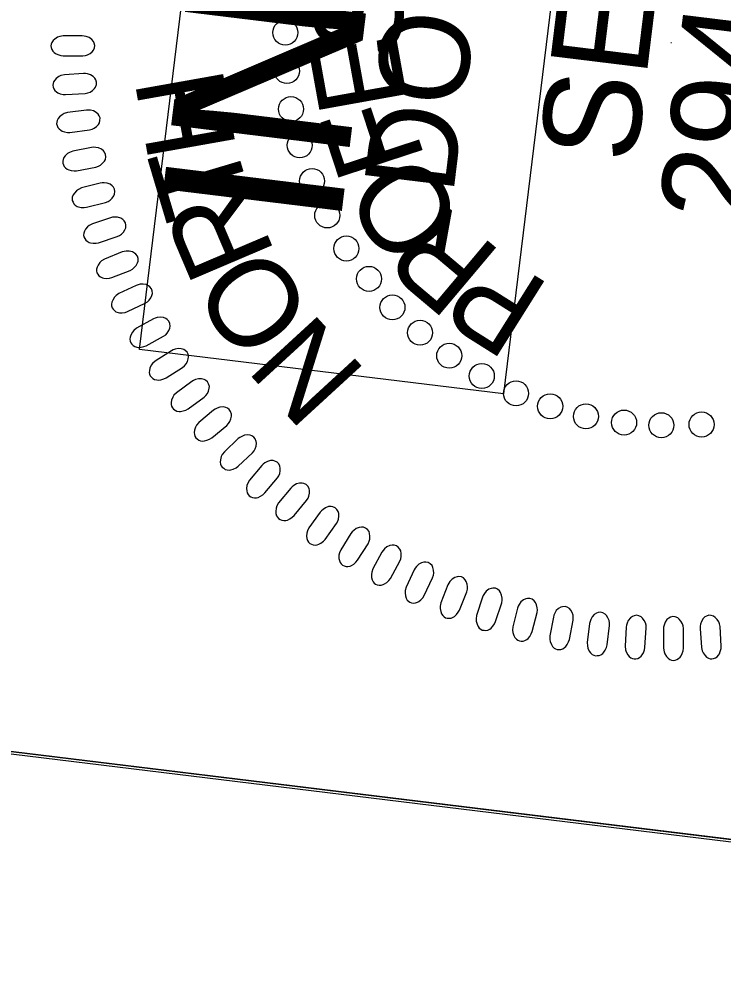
# Model space of a CAD drawing. Extents: x 480570 to 481861, y 488765 to 490569.
# Drawn here: x 480835.4 to 480880.5, y 490328.8 to 490389.3 of the extents above; entities that cross this region are included whole.
import ezdxf

# ---------------------------------------------------------------- set-up
doc = ezdxf.new("R2010")
doc.units = 0
for name, color, linetype in [('Sheet Clip Boundary CELL', 7, 'Continuous'), ('Sheet PE Seal Cell', 7, 'Continuous'), ('Sheet Plan CELL', 7, 'Continuous'), ('Sheet Sticker Incomplete CELL', 7, 'Continuous')]:
    doc.layers.add(name, color=color, linetype=linetype)

msp = doc.modelspace()

# ---------------------------------------------------------------- linework, layer by layer
at = {"layer": 'Sheet Clip Boundary CELL'}
msp.add_lwpolyline([(481654.789, 488932.477), (481815.956, 490252.137), (481655.102, 490245.276), (481542.679, 490356.599), (481123.704, 490407.772), (480954.544, 490428.587), (480942.398, 490329.137), (480942.398, 490329.137), (480770.14, 490350.174), (480612.545, 489059.764)], close=True, dxfattribs=at)
at = {"layer": 'Sheet PE Seal Cell'}
msp.add_line((480877.203, 490387.81), (480877.249, 490387.805), dxfattribs=at)
for points in [[(480839.503, 490388.241), (480838.276, 490388.237), (480838.057, 490388.199), (480837.918, 490388.146), (480837.748, 490388.033), (480837.639, 490387.935), (480837.56, 490387.823), (480837.52, 490387.718), (480837.5, 490387.606), (480837.521, 490387.494), (480837.551, 490387.374), (480837.611, 490387.27), (480837.712, 490387.165), (480837.792, 490387.106), (480837.941, 490387.039), (480838.121, 490386.98), (480838.281, 490386.958), (480839.537, 490386.956), (480839.707, 490386.979), (480839.847, 490387.024), (480840.006, 490387.114), (480840.145, 490387.227), (480840.224, 490387.325), (480840.284, 490387.482), (480840.303, 490387.631), (480840.263, 490387.78), (480840.212, 490387.885), (480840.112, 490388.012), (480839.942, 490388.131), (480839.762, 490388.197), (480839.633, 490388.226)], [(480839.579, 490385.833), (480838.356, 490385.752), (480838.139, 490385.7), (480838.003, 490385.638), (480837.841, 490385.515), (480837.739, 490385.411), (480837.666, 490385.294), (480837.634, 490385.187), (480837.621, 490385.073), (480837.648, 490384.963), (480837.686, 490384.846), (480837.753, 490384.745), (480837.86, 490384.647), (480837.943, 490384.593), (480838.097, 490384.536), (480838.28, 490384.488), (480838.44, 490384.476), (480839.695, 490384.552), (480839.863, 490384.586), (480839.999, 490384.64), (480840.152, 490384.74), (480840.284, 490384.861), (480840.357, 490384.964), (480840.406, 490385.124), (480840.416, 490385.274), (480840.366, 490385.421), (480840.31, 490385.522), (480840.202, 490385.642), (480840.025, 490385.751), (480839.841, 490385.806), (480839.71, 490385.826)], [(480839.768, 490383.487), (480838.552, 490383.329), (480838.339, 490383.264), (480838.207, 490383.194), (480838.054, 490383.061), (480837.958, 490382.95), (480837.893, 490382.829), (480837.866, 490382.72), (480837.861, 490382.606), (480837.895, 490382.497), (480837.941, 490382.383), (480838.014, 490382.287), (480838.126, 490382.196), (480838.213, 490382.147), (480838.37, 490382.099), (480838.556, 490382.063), (480838.717, 490382.061), (480839.964, 490382.216), (480840.129, 490382.26), (480840.262, 490382.323), (480840.408, 490382.433), (480840.533, 490382.562), (480840.599, 490382.668), (480840.638, 490382.832), (480840.639, 490382.983), (480840.58, 490383.126), (480840.517, 490383.223), (480840.401, 490383.336), (480840.218, 490383.433), (480840.031, 490383.476), (480839.899, 490383.489)], [(480840.101, 490381.096), (480838.897, 490380.861), (480838.689, 490380.783), (480838.562, 490380.705), (480838.417, 490380.563), (480838.328, 490380.446), (480838.271, 490380.321), (480838.252, 490380.21), (480838.254, 490380.097), (480838.294, 490379.99), (480838.347, 490379.879), (480838.425, 490379.788), (480838.543, 490379.704), (480838.633, 490379.66), (480838.793, 490379.623), (480838.98, 490379.598), (480839.142, 490379.607), (480840.376, 490379.839), (480840.538, 490379.894), (480840.667, 490379.965), (480840.806, 490380.083), (480840.922, 490380.22), (480840.982, 490380.33), (480841.01, 490380.496), (480841.001, 490380.647), (480840.934, 490380.786), (480840.865, 490380.879), (480840.743, 490380.985), (480840.553, 490381.07), (480840.364, 490381.101), (480840.231, 490381.106)], [(480840.645, 490378.812), (480839.458, 490378.503), (480839.255, 490378.411), (480839.133, 490378.326), (480838.997, 490378.174), (480838.915, 490378.053), (480838.867, 490377.924), (480838.854, 490377.813), (480838.864, 490377.699), (480838.911, 490377.595), (480838.97, 490377.487), (480839.054, 490377.401), (480839.177, 490377.325), (480839.27, 490377.287), (480839.432, 490377.26), (480839.62, 490377.247), (480839.78, 490377.266), (480840.998, 490377.576), (480841.156, 490377.64), (480841.28, 490377.719), (480841.412, 490377.846), (480841.519, 490377.989), (480841.572, 490378.104), (480841.59, 490378.271), (480841.571, 490378.421), (480841.495, 490378.555), (480841.42, 490378.643), (480841.292, 490378.742), (480841.098, 490378.815), (480840.907, 490378.834), (480840.774, 490378.831)], [(480841.314, 490376.597), (480840.149, 490376.214), (480839.952, 490376.11), (480839.836, 490376.016), (480839.709, 490375.857), (480839.636, 490375.73), (480839.595, 490375.599), (480839.59, 490375.487), (480839.606, 490375.374), (480839.66, 490375.274), (480839.726, 490375.17), (480839.815, 490375.089), (480839.943, 490375.021), (480840.037, 490374.989), (480840.2, 490374.972), (480840.39, 490374.971), (480840.548, 490375), (480841.744, 490375.386), (480841.898, 490375.46), (480842.017, 490375.546), (480842.14, 490375.681), (480842.238, 490375.832), (480842.283, 490375.948), (480842.291, 490376.116), (480842.263, 490376.265), (480842.178, 490376.394), (480842.098, 490376.478), (480841.964, 490376.567), (480841.766, 490376.628), (480841.574, 490376.636), (480841.441, 490376.624)], [(480842.068, 490374.407), (480840.929, 490373.95), (480840.739, 490373.834), (480840.629, 490373.734), (480840.513, 490373.567), (480840.447, 490373.436), (480840.415, 490373.303), (480840.417, 490373.191), (480840.44, 490373.079), (480840.5, 490372.982), (480840.572, 490372.882), (480840.666, 490372.807), (480840.798, 490372.747), (480840.894, 490372.721), (480841.058, 490372.714), (480841.248, 490372.725), (480841.404, 490372.764), (480842.573, 490373.224), (480842.722, 490373.308), (480842.835, 490373.402), (480842.949, 490373.544), (480843.038, 490373.7), (480843.076, 490373.82), (480843.073, 490373.988), (480843.036, 490374.134), (480842.944, 490374.258), (480842.858, 490374.337), (480842.718, 490374.418), (480842.517, 490374.465), (480842.325, 490374.462), (480842.194, 490374.441)], [(480842.957, 490372.266), (480841.849, 490371.739), (480841.666, 490371.611), (480841.563, 490371.504), (480841.457, 490371.33), (480841.4, 490371.195), (480841.376, 490371.06), (480841.385, 490370.948), (480841.415, 490370.838), (480841.481, 490370.745), (480841.56, 490370.651), (480841.658, 490370.582), (480841.793, 490370.53), (480841.891, 490370.51), (480842.056, 490370.513), (480842.243, 490370.537), (480842.397, 490370.584), (480843.535, 490371.117), (480843.679, 490371.21), (480843.786, 490371.311), (480843.891, 490371.46), (480843.969, 490371.621), (480844, 490371.743), (480843.986, 490371.911), (480843.94, 490372.054), (480843.84, 490372.172), (480843.75, 490372.246), (480843.606, 490372.318), (480843.401, 490372.353), (480843.21, 490372.336), (480843.08, 490372.308)], [(480844.059, 490370.116), (480842.986, 490369.52), (480842.812, 490369.381), (480842.715, 490369.268), (480842.621, 490369.087), (480842.573, 490368.949), (480842.557, 490368.813), (480842.573, 490368.701), (480842.61, 490368.594), (480842.682, 490368.506), (480842.766, 490368.416), (480842.869, 490368.353), (480843.007, 490368.31), (480843.106, 490368.296), (480843.27, 490368.31), (480843.455, 490368.345), (480843.606, 490368.403), (480844.708, 490369.005), (480844.846, 490369.108), (480844.946, 490369.214), (480845.042, 490369.37), (480845.11, 490369.536), (480845.133, 490369.66), (480845.108, 490369.826), (480845.053, 490369.966), (480844.946, 490370.078), (480844.852, 490370.145), (480844.703, 490370.208), (480844.496, 490370.23), (480844.307, 490370.202), (480844.179, 490370.165)], [(480845.209, 490368.08), (480844.176, 490367.419), (480844.011, 490367.269), (480843.922, 490367.15), (480843.84, 490366.964), (480843.799, 490366.824), (480843.792, 490366.686), (480843.816, 490366.576), (480843.859, 490366.471), (480843.937, 490366.387), (480844.026, 490366.303), (480844.133, 490366.246), (480844.274, 490366.212), (480844.373, 490366.205), (480844.535, 490366.229), (480844.718, 490366.275), (480844.866, 490366.343), (480845.928, 490367.013), (480846.058, 490367.124), (480846.152, 490367.237), (480846.238, 490367.398), (480846.295, 490367.568), (480846.31, 490367.693), (480846.275, 490367.857), (480846.211, 490367.994), (480846.097, 490368.098), (480845.999, 490368.16), (480845.847, 490368.213), (480845.639, 490368.222), (480845.452, 490368.182), (480845.326, 490368.137)], [(480846.52, 490366.119), (480845.53, 490365.394), (480845.375, 490365.235), (480845.293, 490365.11), (480845.223, 490364.919), (480845.192, 490364.776), (480845.193, 490364.639), (480845.223, 490364.53), (480845.273, 490364.428), (480845.356, 490364.35), (480845.451, 490364.271), (480845.561, 490364.221), (480845.703, 490364.196), (480845.803, 490364.195), (480845.963, 490364.229), (480846.143, 490364.287), (480846.285, 490364.363), (480847.304, 490365.1), (480847.427, 490365.217), (480847.513, 490365.336), (480847.589, 490365.503), (480847.636, 490365.677), (480847.643, 490365.802), (480847.598, 490365.964), (480847.525, 490366.096), (480847.405, 490366.193), (480847.303, 490366.248), (480847.148, 490366.292), (480846.94, 490366.288), (480846.755, 490366.236), (480846.633, 490366.184)], [(480847.916, 490364.274), (480846.974, 490363.489), (480846.829, 490363.319), (480846.755, 490363.19), (480846.696, 490362.995), (480846.674, 490362.85), (480846.685, 490362.713), (480846.722, 490362.607), (480846.778, 490362.508), (480846.865, 490362.435), (480846.965, 490362.362), (480847.077, 490362.32), (480847.221, 490362.303), (480847.321, 490362.309), (480847.479, 490362.352), (480847.655, 490362.422), (480847.792, 490362.506), (480848.762, 490363.305), (480848.878, 490363.431), (480848.956, 490363.555), (480849.021, 490363.726), (480849.057, 490363.901), (480849.056, 490364.027), (480849.002, 490364.186), (480848.921, 490364.314), (480848.794, 490364.403), (480848.69, 490364.451), (480848.531, 490364.485), (480848.324, 490364.469), (480848.143, 490364.405), (480848.025, 490364.345)], [(480849.494, 490362.456), (480848.603, 490361.613), (480848.469, 490361.435), (480848.403, 490361.301), (480848.357, 490361.103), (480848.344, 490360.957), (480848.364, 490360.821), (480848.406, 490360.718), (480848.469, 490360.622), (480848.561, 490360.554), (480848.665, 490360.488), (480848.78, 490360.453), (480848.924, 490360.446), (480849.023, 490360.457), (480849.178, 490360.511), (480849.35, 490360.591), (480849.481, 490360.684), (480850.399, 490361.542), (480850.507, 490361.675), (480850.577, 490361.804), (480850.632, 490361.979), (480850.656, 490362.156), (480850.647, 490362.282), (480850.582, 490362.437), (480850.495, 490362.558), (480850.363, 490362.64), (480850.255, 490362.682), (480850.095, 490362.706), (480849.89, 490362.676), (480849.713, 490362.602), (480849.598, 490362.534)], [(480850.998, 490360.736), (480850.213, 490359.794), (480850.101, 490359.601), (480850.051, 490359.461), (480850.029, 490359.259), (480850.033, 490359.112), (480850.068, 490358.98), (480850.123, 490358.882), (480850.197, 490358.795), (480850.295, 490358.738), (480850.407, 490358.685), (480850.525, 490358.663), (480850.669, 490358.673), (480850.766, 490358.696), (480850.914, 490358.768), (480851.075, 490358.867), (480851.194, 490358.975), (480852.005, 490359.935), (480852.096, 490360.08), (480852.151, 490360.216), (480852.185, 490360.396), (480852.188, 490360.575), (480852.164, 490360.698), (480852.082, 490360.845), (480851.98, 490360.956), (480851.84, 490361.021), (480851.728, 490361.05), (480851.566, 490361.055), (480851.366, 490361.001), (480851.199, 490360.907), (480851.093, 490360.826)], [(480852.859, 490359.285), (480852.081, 490358.337), (480851.97, 490358.144), (480851.922, 490358.003), (480851.901, 490357.8), (480851.907, 490357.654), (480851.942, 490357.521), (480851.998, 490357.424), (480852.072, 490357.337), (480852.172, 490357.282), (480852.283, 490357.229), (480852.402, 490357.209), (480852.546, 490357.22), (480852.643, 490357.243), (480852.79, 490357.316), (480852.95, 490357.417), (480853.068, 490357.526), (480853.872, 490358.493), (480853.962, 490358.638), (480854.016, 490358.774), (480854.048, 490358.954), (480854.05, 490359.133), (480854.025, 490359.257), (480853.942, 490359.403), (480853.839, 490359.513), (480853.698, 490359.577), (480853.586, 490359.605), (480853.424, 490359.609), (480853.224, 490359.553), (480853.058, 490359.457), (480852.952, 490359.376)], [(480854.735, 490357.743), (480854.017, 490356.747), (480853.92, 490356.548), (480853.88, 490356.404), (480853.872, 490356.201), (480853.887, 490356.055), (480853.931, 490355.925), (480853.993, 490355.831), (480854.072, 490355.749), (480854.175, 490355.7), (480854.289, 490355.654), (480854.409, 490355.642), (480854.552, 490355.662), (480854.647, 490355.691), (480854.789, 490355.773), (480854.943, 490355.884), (480855.055, 490356), (480855.795, 490357.015), (480855.876, 490357.165), (480855.921, 490357.305), (480855.942, 490357.487), (480855.933, 490357.666), (480855.9, 490357.788), (480855.808, 490357.928), (480855.698, 490358.031), (480855.554, 490358.086), (480855.44, 490358.107), (480855.278, 490358.101), (480855.083, 490358.033), (480854.923, 490357.927), (480854.823, 490357.839)], [(480856.709, 490356.385), (480856.055, 490355.346), (480855.97, 490355.141), (480855.939, 490354.995), (480855.944, 490354.791), (480855.968, 490354.647), (480856.02, 490354.52), (480856.088, 490354.43), (480856.172, 490354.353), (480856.278, 490354.311), (480856.395, 490354.272), (480856.515, 490354.267), (480856.657, 490354.296), (480856.75, 490354.332), (480856.887, 490354.422), (480857.033, 490354.543), (480857.137, 490354.665), (480857.813, 490355.726), (480857.884, 490355.881), (480857.92, 490356.023), (480857.929, 490356.205), (480857.908, 490356.383), (480857.869, 490356.502), (480857.768, 490356.637), (480857.652, 490356.733), (480857.504, 490356.779), (480857.389, 490356.793), (480857.229, 490356.776), (480857.037, 490356.696), (480856.885, 490356.58), (480856.79, 490356.486)], [(480858.698, 490355.195), (480858.111, 490354.118), (480858.039, 490353.907), (480858.017, 490353.76), (480858.035, 490353.557), (480858.068, 490353.414), (480858.128, 490353.291), (480858.202, 490353.206), (480858.29, 490353.134), (480858.398, 490353.099), (480858.518, 490353.068), (480858.638, 490353.07), (480858.777, 490353.107), (480858.868, 490353.149), (480858.999, 490353.248), (480859.137, 490353.377), (480859.233, 490353.506), (480859.841, 490354.606), (480859.902, 490354.766), (480859.93, 490354.91), (480859.928, 490355.093), (480859.896, 490355.269), (480859.849, 490355.386), (480859.74, 490355.514), (480859.618, 490355.602), (480859.468, 490355.639), (480859.351, 490355.645), (480859.192, 490355.619), (480859.007, 490355.527), (480858.861, 490355.401), (480858.773, 490355.301)], [(480860.765, 490354.06), (480860.247, 490352.948), (480860.188, 490352.734), (480860.176, 490352.585), (480860.206, 490352.384), (480860.248, 490352.243), (480860.316, 490352.124), (480860.393, 490352.044), (480860.487, 490351.978), (480860.597, 490351.949), (480860.718, 490351.925), (480860.838, 490351.935), (480860.975, 490351.981), (480861.063, 490352.029), (480861.188, 490352.136), (480861.317, 490352.273), (480861.405, 490352.408), (480861.943, 490353.544), (480861.994, 490353.707), (480862.012, 490353.853), (480861.998, 490354.035), (480861.955, 490354.209), (480861.902, 490354.323), (480861.785, 490354.443), (480861.657, 490354.525), (480861.505, 490354.551), (480861.389, 490354.55), (480861.231, 490354.514), (480861.052, 490354.411), (480860.915, 490354.276), (480860.833, 490354.171)], [(480862.918, 490353.088), (480862.471, 490351.945), (480862.426, 490351.727), (480862.423, 490351.578), (480862.466, 490351.379), (480862.516, 490351.242), (480862.591, 490351.126), (480862.675, 490351.051), (480862.772, 490350.991), (480862.883, 490350.969), (480863.006, 490350.953), (480863.125, 490350.971), (480863.258, 490351.026), (480863.344, 490351.078), (480863.461, 490351.193), (480863.582, 490351.339), (480863.661, 490351.479), (480864.126, 490352.646), (480864.167, 490352.812), (480864.176, 490352.959), (480864.151, 490353.14), (480864.098, 490353.311), (480864.036, 490353.421), (480863.912, 490353.534), (480863.78, 490353.607), (480863.626, 490353.624), (480863.51, 490353.616), (480863.355, 490353.569), (480863.183, 490353.455), (480863.054, 490353.312), (480862.98, 490353.202)], [(480865.135, 490352.302), (480864.76, 490351.134), (480864.729, 490350.913), (480864.735, 490350.764), (480864.791, 490350.568), (480864.849, 490350.434), (480864.932, 490350.324), (480865.019, 490350.254), (480865.12, 490350.201), (480865.233, 490350.186), (480865.356, 490350.178), (480865.474, 490350.202), (480865.604, 490350.266), (480865.685, 490350.323), (480865.796, 490350.445), (480865.907, 490350.598), (480865.977, 490350.743), (480866.369, 490351.938), (480866.398, 490352.106), (480866.398, 490352.252), (480866.362, 490352.431), (480866.298, 490352.599), (480866.229, 490352.704), (480866.098, 490352.809), (480865.962, 490352.874), (480865.807, 490352.882), (480865.692, 490352.866), (480865.541, 490352.81), (480865.375, 490352.685), (480865.256, 490352.535), (480865.188, 490352.42)], [(480867.381, 490351.604), (480867.081, 490350.414), (480867.063, 490350.193), (480867.079, 490350.044), (480867.146, 490349.852), (480867.213, 490349.722), (480867.303, 490349.617), (480867.395, 490349.553), (480867.499, 490349.506), (480867.612, 490349.498), (480867.736, 490349.498), (480867.851, 490349.53), (480867.977, 490349.601), (480868.055, 490349.664), (480868.157, 490349.792), (480868.259, 490349.952), (480868.32, 490350.101), (480868.635, 490351.317), (480868.654, 490351.488), (480868.645, 490351.633), (480868.598, 490351.81), (480868.523, 490351.973), (480868.448, 490352.074), (480868.311, 490352.171), (480868.17, 490352.227), (480868.016, 490352.225), (480867.902, 490352.202), (480867.754, 490352.137), (480867.597, 490352.001), (480867.488, 490351.844), (480867.427, 490351.725)], [(480869.673, 490351.035), (480869.448, 490349.829), (480869.444, 490349.606), (480869.47, 490349.459), (480869.548, 490349.272), (480869.624, 490349.146), (480869.72, 490349.048), (480869.815, 490348.989), (480869.922, 490348.949), (480870.035, 490348.948), (480870.159, 490348.956), (480870.272, 490348.995), (480870.394, 490349.074), (480870.467, 490349.141), (480870.561, 490349.276), (480870.653, 490349.441), (480870.704, 490349.594), (480870.942, 490350.828), (480870.951, 490350.999), (480870.933, 490351.144), (480870.874, 490351.317), (480870.79, 490351.475), (480870.709, 490351.572), (480870.565, 490351.659), (480870.422, 490351.706), (480870.268, 490351.694), (480870.155, 490351.665), (480870.012, 490351.59), (480869.864, 490351.446), (480869.764, 490351.281), (480869.712, 490351.159)], [(480871.991, 490350.621), (480871.842, 490349.403), (480871.852, 490349.181), (480871.887, 490349.036), (480871.977, 490348.854), (480872.061, 490348.733), (480872.163, 490348.64), (480872.261, 490348.588), (480872.37, 490348.554), (480872.484, 490348.561), (480872.606, 490348.576), (480872.717, 490348.622), (480872.833, 490348.709), (480872.902, 490348.781), (480872.988, 490348.921), (480873.069, 490349.092), (480873.11, 490349.247), (480873.271, 490350.494), (480873.269, 490350.665), (480873.241, 490350.809), (480873.171, 490350.978), (480873.077, 490351.13), (480872.991, 490351.222), (480872.842, 490351.3), (480872.696, 490351.338), (480872.543, 490351.316), (480872.433, 490351.279), (480872.294, 490351.197), (480872.155, 490351.043), (480872.067, 490350.872), (480872.021, 490350.747)], [(480874.337, 490350.387), (480874.265, 490349.162), (480874.289, 490348.941), (480874.333, 490348.798), (480874.435, 490348.622), (480874.525, 490348.507), (480874.633, 490348.421), (480874.735, 490348.375), (480874.846, 490348.349), (480874.958, 490348.362), (480875.08, 490348.385), (480875.188, 490348.438), (480875.298, 490348.532), (480875.363, 490348.608), (480875.438, 490348.753), (480875.509, 490348.929), (480875.541, 490349.086), (480875.622, 490350.34), (480875.61, 490350.511), (480875.573, 490350.653), (480875.493, 490350.818), (480875.389, 490350.964), (480875.298, 490351.049), (480875.144, 490351.118), (480874.996, 490351.147), (480874.844, 490351.116), (480874.737, 490351.072), (480874.604, 490350.98), (480874.475, 490350.818), (480874.397, 490350.643), (480874.359, 490350.515)], [(480876.721, 490350.261), (480876.725, 490349.035), (480876.764, 490348.816), (480876.816, 490348.676), (480876.929, 490348.507), (480877.027, 490348.397), (480877.139, 490348.318), (480877.244, 490348.279), (480877.357, 490348.259), (480877.468, 490348.28), (480877.588, 490348.31), (480877.692, 490348.369), (480877.796, 490348.47), (480877.856, 490348.55), (480877.923, 490348.7), (480877.982, 490348.88), (480878.004, 490349.039), (480878.007, 490350.296), (480877.983, 490350.465), (480877.938, 490350.605), (480877.848, 490350.764), (480877.735, 490350.903), (480877.638, 490350.983), (480877.48, 490351.042), (480877.331, 490351.061), (480877.181, 490351.021), (480877.077, 490350.97), (480876.95, 490350.871), (480876.831, 490350.701), (480876.765, 490350.521), (480876.736, 490350.391)], [(480879.069, 490350.31), (480879.151, 490349.086), (480879.203, 490348.87), (480879.264, 490348.734), (480879.388, 490348.572), (480879.492, 490348.469), (480879.609, 490348.397), (480879.716, 490348.364), (480879.829, 490348.352), (480879.939, 490348.379), (480880.057, 490348.417), (480880.158, 490348.483), (480880.255, 490348.59), (480880.31, 490348.673), (480880.367, 490348.827), (480880.415, 490349.011), (480880.427, 490349.171), (480880.35, 490350.425), (480880.316, 490350.593), (480880.262, 490350.73), (480880.162, 490350.882), (480880.041, 490351.015), (480879.939, 490351.088), (480879.779, 490351.137), (480879.627, 490351.147), (480879.481, 490351.097), (480879.38, 490351.041), (480879.26, 490350.932), (480879.152, 490350.755), (480879.097, 490350.571), (480879.076, 490350.44)]]:
    msp.add_lwpolyline(points, close=True, dxfattribs=at)
for centre in [(480852.508, 490388.447), (480852.608, 490385.988), (480852.871, 490383.549), (480853.43, 490381.234), (480854.219, 490378.947), (480855.193, 490376.742), (480856.419, 490374.627), (480857.867, 490372.684), (480859.369, 490370.856), (480861.137, 490369.235), (480863.003, 490367.763), (480865.092, 490366.464), (480867.283, 490365.353), (480869.469, 490364.524), (480871.759, 490363.882), (480874.203, 490363.486), (480876.59, 490363.314), (480879.165, 490363.36)]:
    msp.add_circle(centre, 0.801, dxfattribs=at)
at = {"layer": 'Sheet Plan CELL'}
for points in [[(481654.799, 488932.664), (480612.566, 489059.935), (480770.135, 490350.338), (480919.092, 490332.157), (480943.356, 490530.718), (481836.655, 490421.612)], [(480807.433, 490345.783), (480819.562, 490445.095), (480931.245, 490431.454), (480919.092, 490332.157)]]:
    msp.add_lwpolyline(points, close=True, dxfattribs=at)
at = {"layer": 'Sheet Sticker Incomplete CELL'}
msp.add_lwpolyline([(480866.487, 490365.317), (480843.16, 490368.166), (480860.982, 490514.082), (480884.308, 490511.233)], close=True, dxfattribs=at)

# ---------------------------------------------------------------- texts
at = {"layer": 'Sheet PE Seal Cell'}
for s, height, rotation, p in [('SEAL', 6.2363, 83.01429, (480874.944, 490379.984)), ('29470', 6.2363, 83.01429, (480882.602, 490376.055)), ('S', 5.669, 84.32196, (480859.76, 490386.76)), ('E', 5.669, 100.20156, (480860.376, 490383.897)), ('H', 5.669, 100.08868, (480849.376, 490381.013)), ('F', 5.669, 108.14136, (480861.492, 490380.345)), ('T', 5.669, 106.57804, (480850.39, 490377.687)), ('O', 5.669, 124.02095, (480864.159, 490376.295)), ('R', 5.669, 113.06739, (480851.904, 490374.257)), ('R', 5.669, 139.90055, (480866.479, 490374.285)), ('O', 5.669, 126.04611, (480854.489, 490370.44)), ('P', 5.669, 147.84034, (480869.611, 490372.203)), ('N', 5.669, 132.53546, (480857.81, 490366.663))]:
    msp.add_text(s, height=height, rotation=rotation, dxfattribs=at).set_placement(p)
at = {"layer": 'Sheet Sticker Incomplete CELL'}
for s, height, p in [('INCOMPLETE PLANS', 11.52, (480855.958, 490375.62)), ('DO NOT USE FOR R/W ACQUISITION', 5.76, (480863.251, 490378.003))]:
    msp.add_text(s, height=height, rotation=83.03651, dxfattribs=at).set_placement(p)

doc.saveas('drawing.dxf')
